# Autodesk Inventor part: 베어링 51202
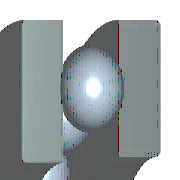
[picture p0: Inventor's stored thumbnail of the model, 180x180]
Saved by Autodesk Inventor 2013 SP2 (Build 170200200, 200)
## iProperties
Created: 2012-02
Part Number: 베어링 51202
Material: 강철, 연강
Description: 롤링 베어링 - 플랫 뒷면이 있는 스러스트 볼 베어링
Document SubType Name: Modeling
Standard: KS B 2022
Designer: mduedu
Standards Organization: KS
Language: ko-KR
Size Designation: 51202 - 15 x 32 x 12
Categories: <MemberInstance><Categories><Category DisplayName="샤프트 부품" InternalName="7f7aeb1f-a693-4053-b835-cee3144e0d98" Mnemonic="SHFT"><Category DisplayName="베어링" Inter
Density: 1 g/cm^3
IsCustomPart: 1
Author: mduedu
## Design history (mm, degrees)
sketch "스케치1" dims "d3" = 5.28 (= 0.44 x KB)
  geometry: L1 (6, 9.61)-(6, 14.89); L2 (8.64, 12.25)-(3.36, 12.25); L3 (3.6, 16)-(0, 16); L4 (3.6, 7.5)-(0, 7.5); L5 (8.4, 13.35)-(8.4, 16); L6 (8.4, 16)-(12, 16); L7 (12, 16)-(12, 8.5); L8 (12, 8.5)-(8.4, 8.5); L9 (8.4, 8.5)-(8.4, 11.15); L10 (3.6, 16)-(3.6, 13.35); L11 (3.6, 11.15)-(3.6, 7.5); L12 (-1.8, 0)-(10.8, 0) reference; L13 (0, -0.022)-(0, 5.522) reference; 1 further point
  constraints: 22 end point, 5 perpendicular, 2 equal length, 2 midpoint, 2 parallel, 2 point on line, 1 collinear, 10 other
  dimensions: "d8" = 4.8 diameter of L11 L1 (= 0.4 x KB); "d11" = 15 diameter of L4 L12 (= WD); "d12" = 17 diameter of L8 L12 (= KAD1); "d13" = 32 diameter of L3 L12 (= KID1); "d14" = 32 diameter of L6 L12 (= BD); "d15" = 24.5 diameter of point (6, 12.25) L12 (= 0.5 x KID1 + 0.5 x KAD1); "d16" = 6 distance from line of point (6, 12.25) L13 (= 0.5 x KB); "d18" = 12 distance between parallel lines of L7 L13 (= KB)
revolve "본체" stored, may be unused: angle "d9" = 90 deg
revolve "볼" stored, may be unused: angle "d10" = 90 deg
pattern_circular "IDS_ARRAYBALL[SIMPL:T]" dims angle "d2" = 360 deg
body "Solid1"
fillet "모깎기1" dims "d4" = 0.6 (= KRS)
fillet "모깎기2" dims "d5" = 0.6 (= KRS)
other parameters: "WD" = 15 [user parameter; used in 2 equation terms], "KAD1" = 17 [user parameter; used in 3 equation terms], "KID1" = 32 [user parameter; used in 3 equation terms], "BD" = 32 [user parameter; used in 2 equation terms], "KB" = 12 [user parameter; used in 6 equation terms], "KRS" = 0.6 [user parameter; used in 2 equation terms], "d0" = 2.4 (= 0.2 x KB), "d6" = 0, "d7" = 0, "d19" = 0, "d41" = 0, "d42" = 0, "WR" = 7.5 (= 0.5 x WD) [user parameter], "BC" = 1.65e+07 [user parameter], "BBA" = 90 deg [user parameter], "BC0" = 2.7e+07 [user parameter], "BR" = 16 (= 0.5 x BD) [user parameter]
